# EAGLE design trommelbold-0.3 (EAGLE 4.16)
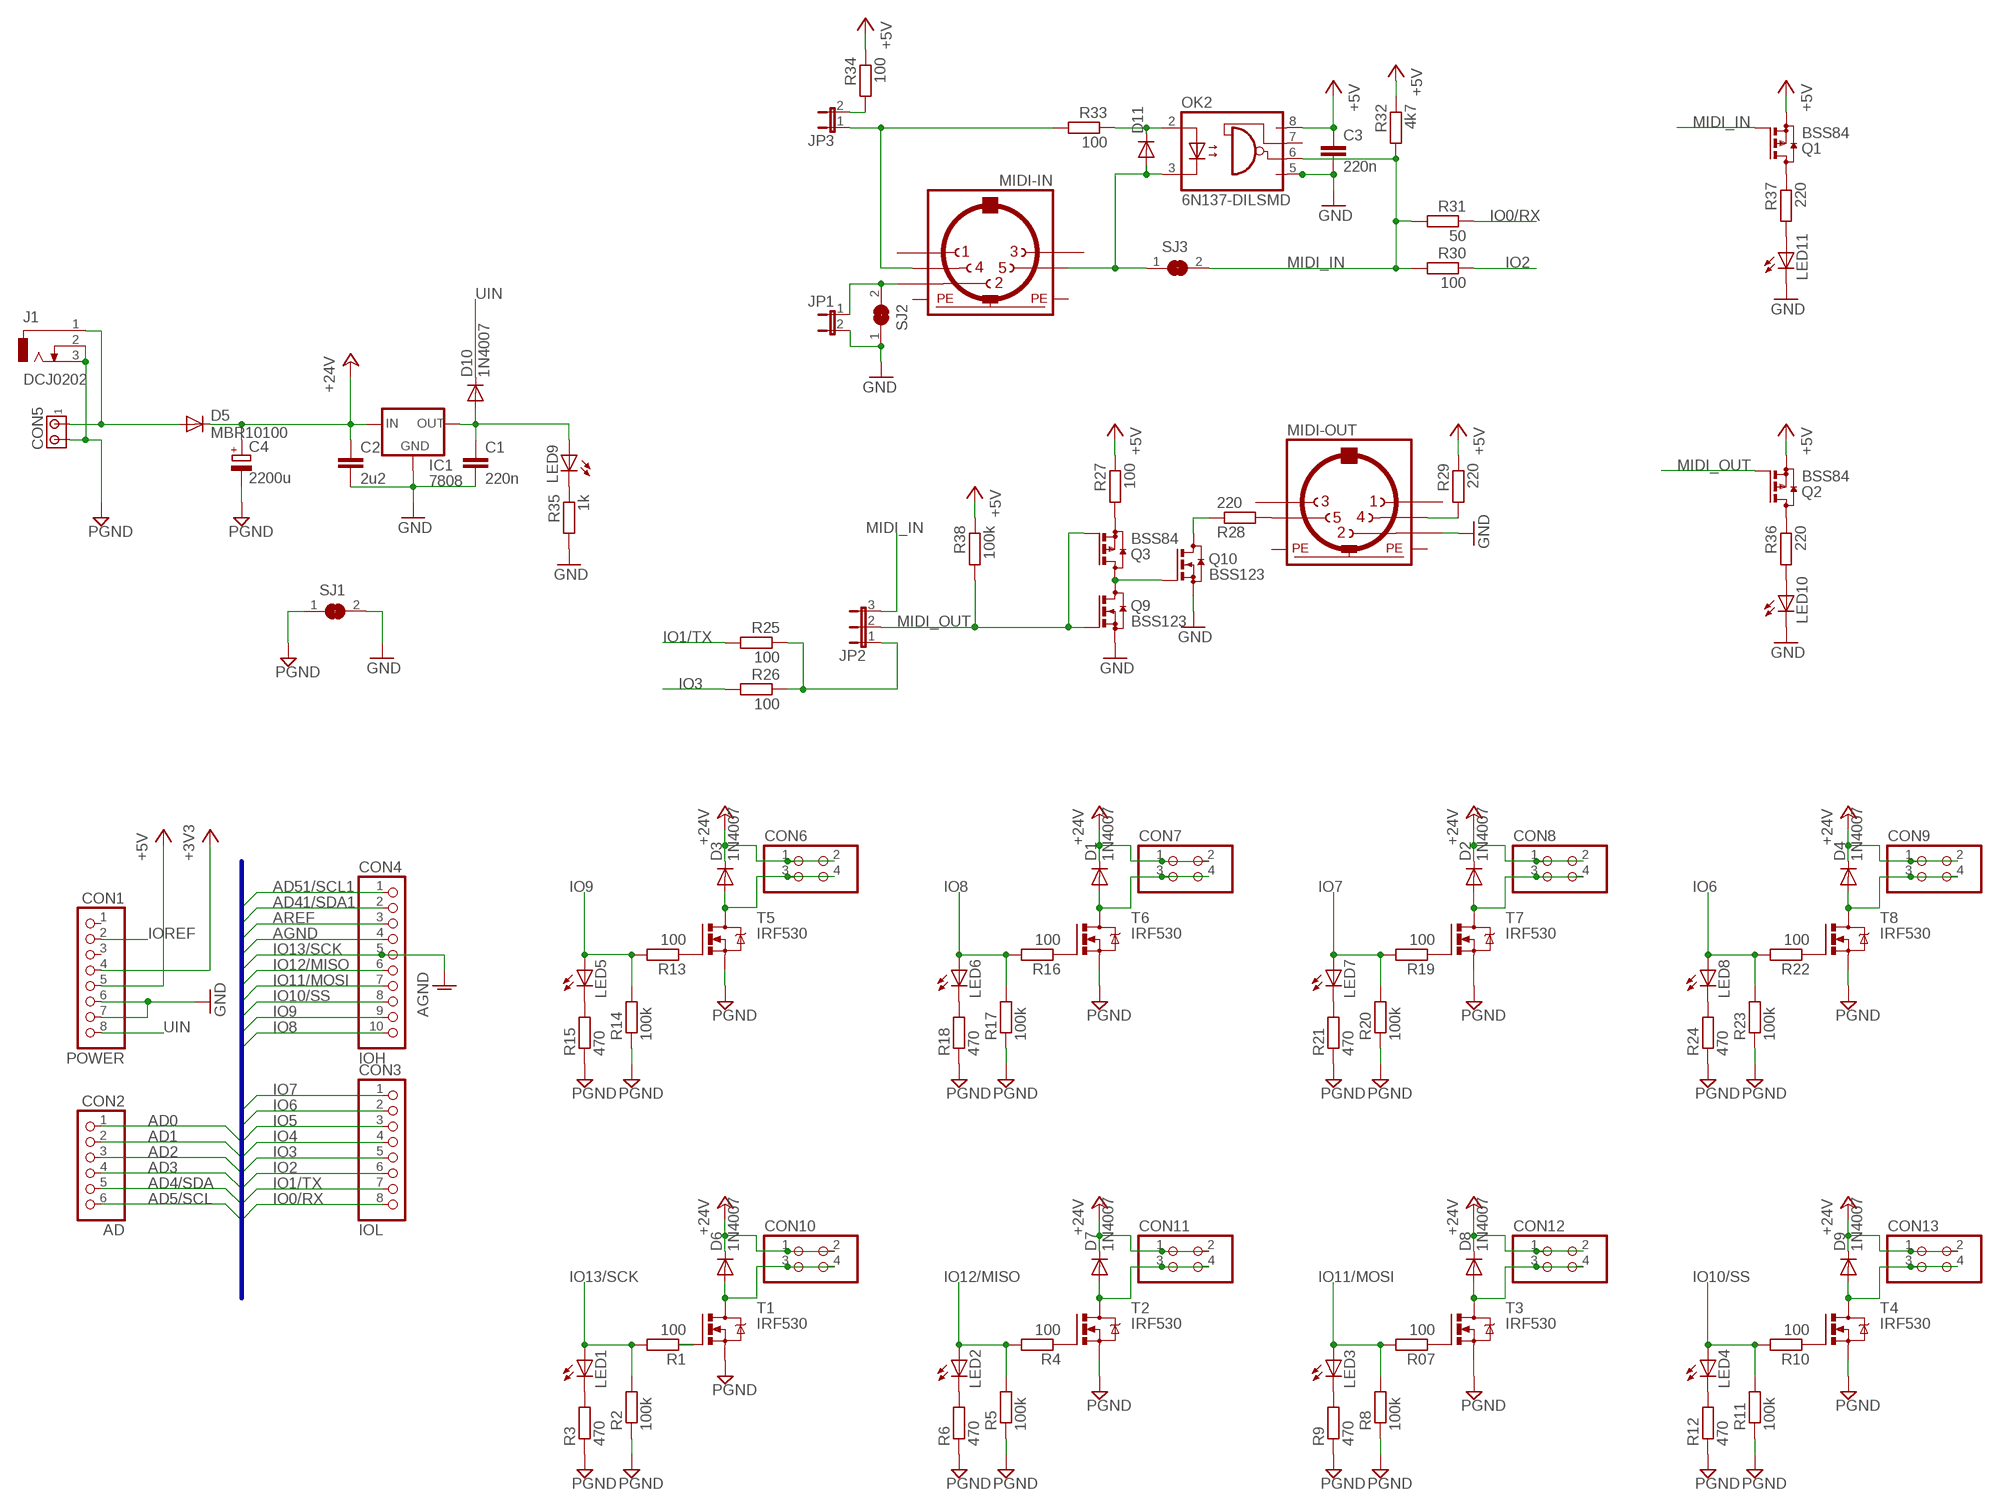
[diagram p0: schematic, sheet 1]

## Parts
C1  220n  C-EUC1206  [C1206]
C2  2u2  C-EUC1206  [C1206]
C3  220n  C-EUC1206  [C1206]
C4  2200u  CPOL-EUE7.5-18  [E7,5-18]
CON1  POWER  PINHD-1X8-L  [1X08-L]
CON2  AD  PINHD-1X6-L  [1X06-L]
CON3  IOL  PINHD-1X8-L  [1X08-L]
CON4  IOH  PINHD-1X10-L  [1X10-L]
CON5  AKL012  SCREW_TERM_X2  [SCREW_TERM_X2_381]
CON6  PINHD-2X2  [2X02]
CON7  PINHD-2X2  [2X02]
CON8  PINHD-2X2  [2X02]
CON9  PINHD-2X2  [2X02]
CON10  PINHD-2X2  [2X02]
CON11  PINHD-2X2  [2X02]
CON12  PINHD-2X2  [2X02]
CON13  PINHD-2X2  [2X02]
D1  1N4007  DIODE-D-7.5  [D-7.5]
D2  1N4007  DIODE-D-7.5  [D-7.5]
D3  1N4007  DIODE-D-7.5  [D-7.5]
D4  1N4007  DIODE-D-7.5  [D-7.5]
D5  MBR10100  DIODE-TO220V  [TO220ACS]
D6  1N4007  DIODE-D-7.5  [D-7.5]
D7  1N4007  DIODE-D-7.5  [D-7.5]
D8  1N4007  DIODE-D-7.5  [D-7.5]
D9  1N4007  DIODE-D-7.5  [D-7.5]
D10  1N4007  DIODE-DO07  [DO07]
D11  DIODE-SOD123  [SOD123]
IC1  7808  78XXS  [78XXS]
J1  DCJ0202  [DCJ0202]
JP1  JP1E  [JP1]
JP2  JP2E  [JP2]
JP3  JP1E  [JP1]
LED1  LED3MM  [LED3MM]
LED2  LED3MM  [LED3MM]
LED3  LED3MM  [LED3MM]
LED4  LED3MM  [LED3MM]
LED5  LED3MM  [LED3MM]
LED6  LED3MM  [LED3MM]
LED7  LED3MM  [LED3MM]
LED8  LED3MM  [LED3MM]
LED9  LED3MM  [LED3MM]
LED10  LED3MM  [LED3MM]
LED11  LED3MM  [LED3MM]
MIDI-IN  MAB5SH  [MAB5SH]
MIDI-OUT  MAB5SH  [MAB5SH]
OK2  6N137-DILSMD  [DIL08-SMD]
Q1  BSS84  [SOT23]
Q2  BSS84  [SOT23]
Q3  BSS84  [SOT23]
Q9  BSS123  [SOT23]
Q10  BSS123  [SOT23]
R1  100  R-EU_M1206  [M1206]
R2  100k  R-EU_M1206  [M1206]
R3  470  R-EU_M1206  [M1206]
R4  100  R-EU_M1206  [M1206]
R5  100k  R-EU_M1206  [M1206]
R6  470  R-EU_M1206  [M1206]
R07  100  R-EU_M1206  [M1206]
R8  100k  R-EU_M1206  [M1206]
R9  470  R-EU_M1206  [M1206]
R10  100  R-EU_M1206  [M1206]
R11  100k  R-EU_M1206  [M1206]
R12  470  R-EU_M1206  [M1206]
R13  100  R-EU_M1206  [M1206]
R14  100k  R-EU_M1206  [M1206]
R15  470  R-EU_M1206  [M1206]
R16  100  R-EU_M1206  [M1206]
R17  100k  R-EU_M1206  [M1206]
R18  470  R-EU_M1206  [M1206]
R19  100  R-EU_M1206  [M1206]
R20  100k  R-EU_M1206  [M1206]
R21  470  R-EU_M1206  [M1206]
R22  100  R-EU_M1206  [M1206]
R23  100k  R-EU_M1206  [M1206]
R24  470  R-EU_M1206  [M1206]
R25  100  R-EU_M1206  [M1206]
R26  100  R-EU_M1206  [M1206]
R27  100  R-EU_M1206  [M1206]
R28  220  R-EU_M1206  [M1206]
R29  220  R-EU_M1206  [M1206]
R30  100  R-EU_M1206  [M1206]
R31  50  R-EU_M1206  [M1206]
R32  4k7  R-EU_M1206  [M1206]
R33  100  R-EU_M1206  [M1206]
R34  100  R-EU_M1206  [M1206]
R35  1k  R-EU_M1206  [M1206]
R36  220  R-EU_M1206  [M1206]
R37  220  R-EU_M1206  [M1206]
R38  100k  R-EU_M1206  [M1206]
SJ1  SJ-CLOSED  [SJ]
SJ2  SJ-CLOSED  [SJ]
SJ3  SJ-CLOSED  [SJ]
T1  IRF530  [TO220BV]
T2  IRF530  [TO220BV]
T3  IRF530  [TO220BV]
T4  IRF530  [TO220BV]
T5  IRF530  [TO220BV]
T6  IRF530  [TO220BV]
T7  IRF530  [TO220BV]
T8  IRF530  [TO220BV]

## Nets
+3V3: CON1.4
+5V: C3.1 CON1.5 OK2.8(VCC) Q1.2(S) Q2.2(S) R27.1 R29.1 R32.1 R34.1 R38.1
+24V: C2.1 C4.+ CON6.1 CON6.2 CON7.1 CON7.2 CON8.1 CON8.2 CON9.1 CON9.2 CON10.1 CON10.2 CON11.1 CON11.2 CON12.1 CON12.2 CON13.1 CON13.2 D1.C D2.C D3.C D4.C D5.C D6.C D7.C D8.C D9.C IC1.IN
AD0: CON2.1
AD1: CON2.2
AD2: CON2.3
AD3: CON2.4
AD4/SDA: CON2.5
AD5/SCL: CON2.6
AD41/SDA1: CON4.2
AD51/SCL1: CON4.1
AGND: CON4.4
AREF: CON4.3
GND: C1.2 C2.2 C3.2 CON1.6 CON1.7 IC1.GND JP1.2 LED10.K(C) LED11.K(C) MIDI-OUT.2 OK2.5(GND) Q9.2(S) Q10.2(S) R35.2 SJ1.2 SJ2.1
GND1: C4.- CON5.2 J1.2 J1.3 R2.1 R3.1 R5.1 R6.1 R8.1 R9.1 R11.1 R12.1 R14.1 R15.1 R17.1 R18.1 R20.1 R21.1 R23.1 R24.1 SJ1.1 T1.S T2.S T3.S T4.S T5.S T6.S T7.S T8.S ; supply symbol labelled PGND
IO0/RX: CON3.8 R31.1
IO1/TX: CON3.7 R25.2
IO2: CON3.6 R30.1
IO3: CON3.5 R26.2
IO4: CON3.4
IO5: CON3.3
IO6: CON3.2 LED8.A R22.2 R23.2
IO7: CON3.1 LED7.A R19.2 R20.2
IO8: CON4.10 LED6.A R16.2 R17.2
IO9: CON4.9 LED5.A R13.2 R14.2
IO10/SS: CON4.8 LED4.A R10.2 R11.2
IO11/MOSI: CON4.7 LED3.A R07.2 R8.2
IO12/MISO: CON4.6 LED2.A R4.2 R5.2
IO13/SCK: CON4.5 LED1.A R1.2 R2.2 ; supply symbol labelled AGND
IOREF: CON1.2
MIDI_IN: JP2.3 OK2.6(VO) Q1.1(G) R30.2 R31.2 R32.2 SJ3.2
MIDI_OUT: JP2.2 Q2.1(G) Q3.1(G) Q9.1(G) R38.2
N$1: CON8.3 CON8.4 D2.A T7.D
N$2: CON6.3 CON6.4 D3.A T5.D
N$3: CON7.3 CON7.4 D1.A T6.D
N$4: CON9.3 CON9.4 D4.A T8.D
N$6: R19.1 T7.G
N$7: CON5.1 D5.A J1.1
N$8: R22.1 T8.G
N$9: CON10.3 CON10.4 D6.A T1.D
N$10: CON11.3 CON11.4 D7.A T2.D
N$11: CON12.3 CON12.4 D8.A T3.D
N$12: CON13.3 CON13.4 D9.A T4.D
N$13: R07.1 T3.G
N$14: R10.1 T4.G
N$15: JP3.1 MIDI-IN.4 R33.2
N$16: R1.1 T1.G
N$17: D11.C OK2.2(A) R33.1
N$18: JP3.2 R34.2
N$19: Q3.3(D) Q9.3(D) Q10.1(G)
N$20: R13.1 T5.G
N$21: R16.1 T6.G
N$22: MIDI-OUT.4 R29.2
N$23: Q10.3(D) R28.1
N$24: MIDI-OUT.5 R28.2
N$25: Q1.3(D) R37.1
N$29: LED3.K(C) R9.2
N$30: LED11.A R37.2
N$31: LED1.K(C) R3.2
N$32: JP2.1 R25.1 R26.1
N$33: LED2.K(C) R6.2
N$34: LED4.K(C) R12.2
N$35: LED8.K(C) R24.2
N$36: LED7.K(C) R21.2
N$37: LED6.K(C) R18.2
N$38: LED5.K(C) R15.2
N$40: C1.1 D10.A IC1.OUT LED9.A
N$44: R4.1 T2.G
N$45: Q2.3(D) R36.1
N$46: D11.A MIDI-IN.5 OK2.3(C) SJ3.1
N$47: LED9.K(C) R35.1
N$48: LED10.A R36.2
N$50: Q3.2(S) R27.2
N$51: JP1.1 MIDI-IN.2 SJ2.2
UIN: CON1.8 D10.C
Unconnected: CON1.1 CON1.3 MIDI-IN.1 MIDI-IN.3 MIDI-OUT.1 MIDI-OUT.3 OK2.7(VE)

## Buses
RESET,AD0,AD1,AD2,AD3,AD4/SDA,AD5/SCL,IO0/RX,IO1/TX,IO2,IO3,IO4,IO5,IO6,IO7,IO8,IO9,IO10/SS,IO11/MOSI,IO12/MISO,IO13/SCK,AREF,AGND,AD41/SDA1,AD51/SCL1

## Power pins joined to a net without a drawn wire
PE: MIDI-IN.PE MIDI-IN.PE@(PE) MIDI-OUT.PE MIDI-OUT.PE@(PE)

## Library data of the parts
C1-C3 = rcl:C-EU: CAPACITOR, European symbol
C4 = rcl:CPOL-EU: POLARIZED CAPACITOR, European symbol
CON1 CON3 = 00_pinhead_small:PINHD-1X8: PIN HEADER
CON2 = 00_pinhead_small:PINHD-1X6: PIN HEADER
CON4 = 00_pinhead_small:PINHD-1X10: PIN HEADER
CON5 = 00_sm_con:SCREW_TERM_X2
CON6-CON13 = pinhead:PINHD-2X2: PIN HEADER
D1-D11 = diode:DIODE-: DIODE
IC1 = v-reg:78XXS: VOLTAGE REGULATOR
J1 = 00_sm_con:DCJ0202: DC POWER JACK Source: DCJ0202.pdf
JP1 JP3 = jumper:JP1E: JUMPER
JP2 = jumper:JP2E: JUMPER
LED1-LED11 = led:LED: LED
MIDI-IN MIDI-OUT = con-hirschmann:MAB5SH: Female CONNECTOR 5 pins 90 deg. with shield, horizontal (DIN 41524)
OK2 = 00_sm_div:6N137: MOTOROLA OPTO COUPLER
Q1-Q3 = transistor-small-signal:BSS84: P-CHANNEL MOS FET
Q9 Q10 = transistor-small-signal:BSS123: N-CHANNEL MOS FET
R1-R6 R07 R8-R38 = rcl:R-EU_: RESISTOR, European symbol
SJ1-SJ3 = 00_sm_div:SJ-CLOSED: SMD solder JUMPER
T1-T8 = transistor-power:IRF530: HEXFET Power MOSFET

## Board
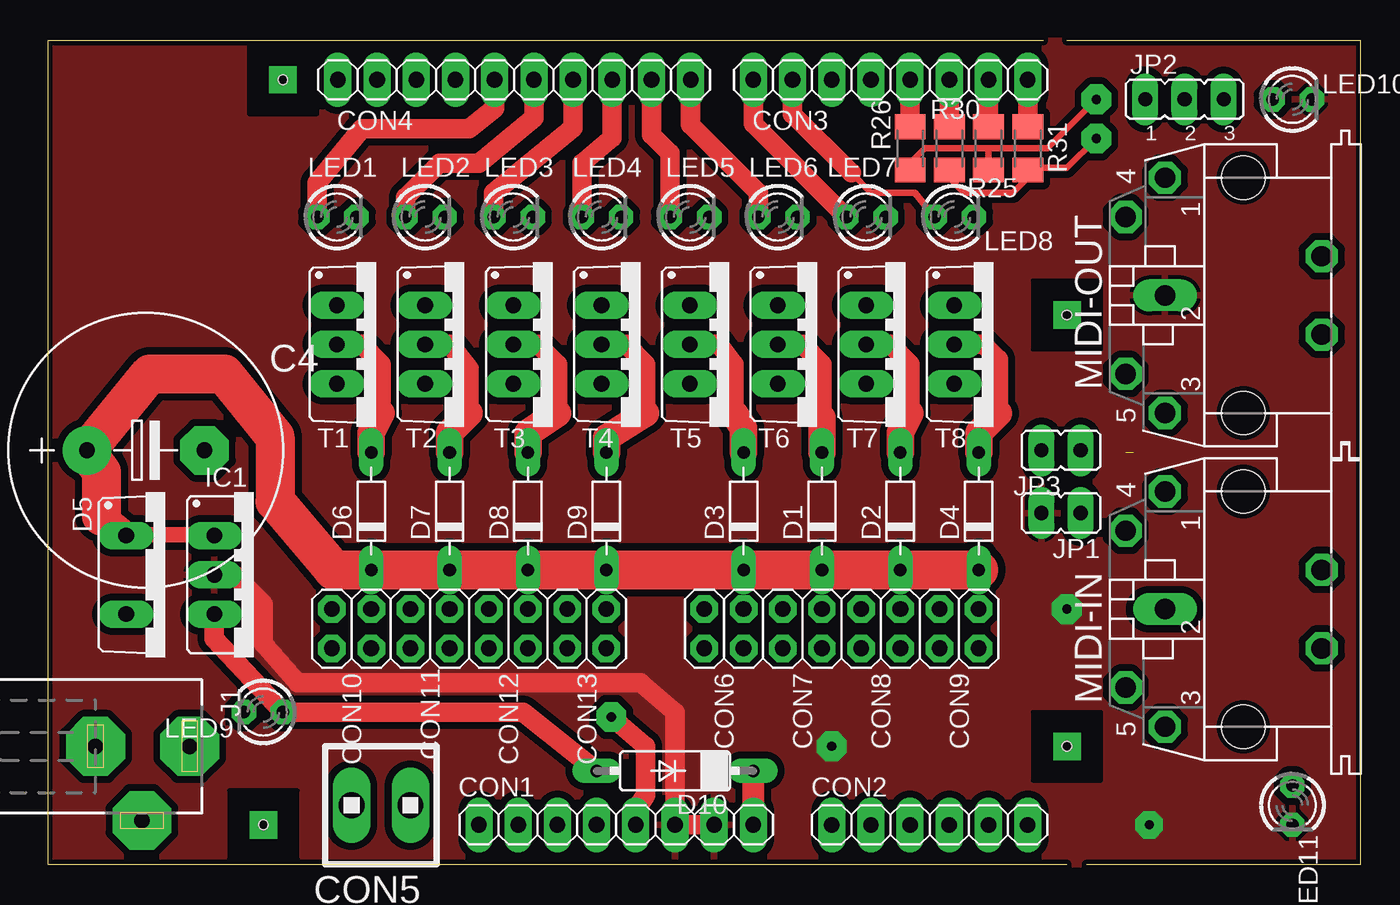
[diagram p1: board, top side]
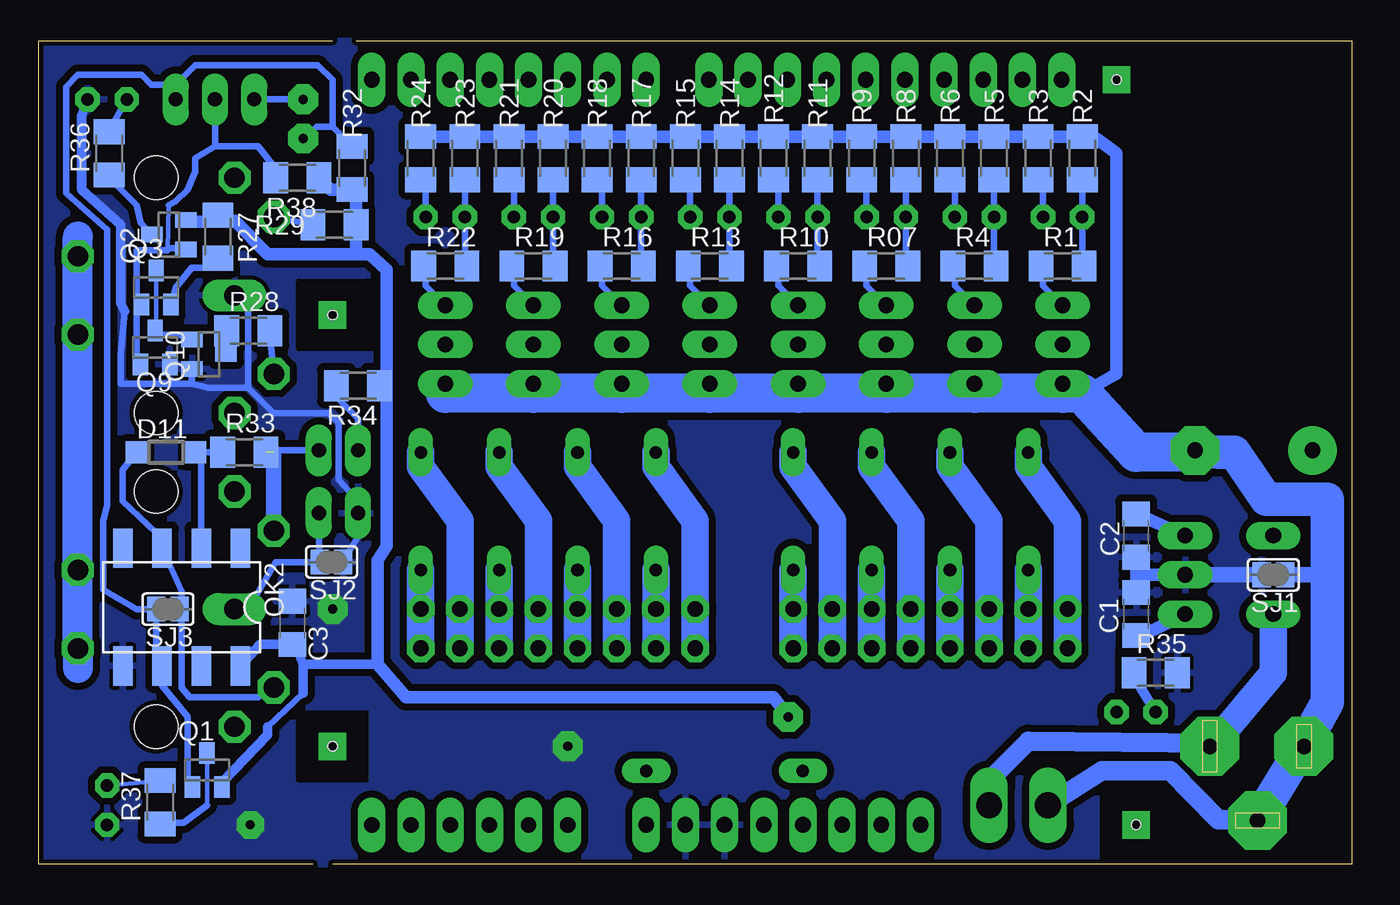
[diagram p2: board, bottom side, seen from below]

Size 85.09 x 53.34 mm. Coordinates in mm from the lower left corner, seen from the top.
Outline: 66.04,0 0,0 0,53.34 64.52,53.34
Outline: 67.31,0 85.09,0 85.09,53.34 66.04,53.34
Copper layers (1*16): Top 0.035mm / dielectric 1.5mm / Bottom 0.035mm
Design rules "default": minimum track width 10mil, minimum drill 24mil, track to track 18mil, track to pad 18mil, pad to pad 18mil, via to via 18mil, smd to smd 18mil, copper to edge 12mil, drill to drill 8mil, minimum pad ring 15mil, minimum via ring 8mil, stop-mask expansion 4mil, vias tented up to drill 0mil, thermal gap 10mil
Holes 0.6 mm at 13.97,2.54 66.04,7.62 66.04,35.56 15.24,50.8
tRestrict: area 13,48.6 to 17.5,53; area 63.8,5.4 to 68.3,9.8; area 63.8,33.3 to 68.3,37.8; area 11.7,0.3 to 16.2,4.8
bRestrict: area -1.3,28.9 to 11.4,46; area 13,48.6 to 17.5,53; area 11.7,0.3 to 16.2,4.8; area 63.8,33.3 to 68.3,37.8; area 63.8,5.4 to 68.3,9.8

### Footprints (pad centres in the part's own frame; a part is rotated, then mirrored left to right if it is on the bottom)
C1206 = smd 1.6 x 1.8: 1 -1.4,0; 2 1.4,0
E7,5-18 = drill 1.016 pad 3.15 round: + -3.81,0 | drill 1.016 pad 3.15 octagon: - 3.81,0
1X08-L = drill 1.016 pad 1.778 long: 1 -8.89,0; 2 -6.35,0; 3 -3.81,0; 4 -1.27,0; 5 1.27,0; 6 3.81,0; 7 6.35,0; 8 8.89,0
1X06-L = drill 1 pad 1.778 long: 1 -6.35,0; 2 -3.81,0; 3 -1.27,0; 4 1.27,0; 5 3.81,0; 6 6.35,0
1X10-L = drill 1.016 pad 1.778 long: 1 -11.43,0; 2 -8.89,0; 3 -6.35,0; 4 -3.81,0; 5 -1.27,0; 6 1.27,0; 7 3.81,0; 8 6.35,0; 9 8.89,0; 10 11.43,0
SCREW_TERM_X2_381 = drill 1.676 long: 1 1.905,0; 2 -1.905,0
2X02 = drill 1.016 octagon: 1 -1.27,-1.27; 2 -1.27,1.27; 3 1.27,-1.27; 4 1.27,1.27
D-7.5 = drill 0.813 long: A 3.81,0; C -3.81,0
TO220ACS = drill 1.016 long: A 2.54,-2.54; C -2.54,-2.54
DO07 = drill 0.813 long: A 5.08,0; C -5.08,0
SOD123 = smd 1.4 x 1.4: A 1.9,0; C -1.9,0
78XXS = drill 1.016 long: GND 0,-2.54; IN -2.54,-2.54; OUT 2.54,-2.54
DCJ0202 = drill 1 pad 3.81 octagon: 1 0,3.1; 2 4.8,0; 3 0,-3
JP1 = drill 0.914 long: 1 0,-1.27; 2 0,1.27
JP2 = drill 0.914 long: 1 -2.54,0; 2 0,0; 3 2.54,0
LED3MM = drill 0.813 octagon: A -1.27,0; K 1.27,0
MAB5SH = drill 1.321 octagon: 1 7.62,5.08; 3 -7.62,5.08; 4 5.08,7.62; 5 -5.08,7.62; PE -2.54,-5.08; PE@ 2.54,-5.08 | drill 1.321 long: 2 0,5.08 | hole 2.794: 7.62,0; -7.62,0
DIL08-SMD = smd 1.27 x 2.54: 1 -3.81,-3.81; 2 -1.27,-3.81; 3 1.27,-3.81; 4 3.81,-3.81; 5 3.81,3.81; 6 1.27,3.81; 7 -1.27,3.81; 8 -3.81,3.81
SOT23 = smd 1 x 1.4: 1 -0.95,-1.1; 2 0.95,-1.1; 3 0,1.1
M1206 = smd 1.6 x 2: 1 -1.4,0; 2 1.4,0
SJ = smd 1.168 x 1.6: 1 -0.762,0; 2 0.762,0
TO220BV = drill 1.016 long: D 0,-2.54; G -2.54,-2.54; S 2.54,-2.54

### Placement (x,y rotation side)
C1  13.97,16.19 90 bottom
C2  13.97,21.27 270 bottom
C3  68.64,15.62 90 bottom
C4  6.35,26.8 0 top
CON1  36.83,2.54 0 top
CON2  57.15,2.54 0 top
CON3  54.61,50.8 0 top
CON4  30.23,50.8 0 top
CON5  21.59,3.81 0 top
CON6  43.81,15.24 180 top
CON7  48.9,15.24 180 top
CON8  53.98,15.24 180 top
CON9  59.05,15.24 180 top
CON10  19.68,15.24 180 top
CON11  24.77,15.24 180 top
CON12  29.84,15.24 180 top
CON13  34.92,15.24 180 top
D1  50.16,22.86 90 top
D2  55.24,22.86 90 top
D3  45.09,22.86 90 top
D4  60.33,22.86 90 top
D5  7.62,18.73 270 top
D6  20.95,22.86 90 top
D7  26.04,22.86 90 top
D8  31.11,22.86 90 top
D9  36.2,22.86 90 top
D10  40.64,6.03 180 top
D11  76.83,26.67 180 bottom
IC1  13.34,18.73 270 top
J1  6.1,7.62 270 top
JP1  65.66,22.73 90 top
JP2  73.66,49.53 0 top
JP3  65.66,26.8 90 top
LED1  18.73,41.91 0 top
LED2  24.45,41.91 0 top
LED3  30.16,41.91 0 top
LED4  35.88,41.91 0 top
LED5  41.59,41.91 0 top
LED6  47.31,41.91 0 top
LED7  53.02,41.91 0 top
LED8  58.74,41.91 0 top
LED9  13.97,9.84 180 top
LED10  80.64,49.53 0 top
LED11  80.64,3.81 270 top
MIDI-IN  77.47,16.51 90 top
MIDI-OUT  77.47,36.83 90 top
OK2  75.82,16.64 180 bottom
Q1  74.17,6.1 0 bottom
Q2  76.64,40.77 90 bottom
Q3  77.47,37.34 0 bottom
Q9  77.53,33.46 0 bottom
Q10  74.04,33.02 270 bottom
R1  18.73,38.73 0 bottom
R2  17.46,45.72 270 bottom
R3  20.32,45.72 270 bottom
R4  24.45,38.73 0 bottom
R5  23.18,45.72 270 bottom
R6  26.04,45.72 270 bottom
R07  30.16,38.73 0 bottom
R8  28.89,45.72 270 bottom
R9  31.75,45.72 270 bottom
R10  35.88,38.73 0 bottom
R11  34.61,45.72 270 bottom
R12  37.47,45.72 270 bottom
R13  41.59,38.73 0 bottom
R14  40.32,45.72 270 bottom
R15  43.18,45.72 270 bottom
R16  47.31,38.73 0 bottom
R17  46.04,45.72 270 bottom
R18  48.9,45.72 270 bottom
R19  53.02,38.73 0 bottom
R20  51.75,45.72 270 bottom
R21  54.61,45.72 270 bottom
R22  58.74,38.73 0 bottom
R23  57.47,45.72 270 bottom
R24  60.33,45.72 270 bottom
R25  60.96,46.35 90 top
R26  55.88,46.35 90 top
R27  73.47,40.64 270 bottom
R28  71.5,34.54 0 bottom
R29  65.91,41.4 180 bottom
R30  58.42,46.35 270 top
R31  63.5,46.35 270 top
R32  64.77,45.09 90 bottom
R33  71.75,26.67 0 bottom
R34  64.39,30.99 180 bottom
R35  12.7,12.38 0 bottom
R36  80.52,46.04 90 bottom
R37  77.22,4 90 bottom
R38  68.33,44.45 180 bottom
SJ1  5.08,18.73 180 bottom
SJ2  66.1,19.56 180 bottom
SJ3  76.71,16.51 180 bottom
T1  21.27,33.66 270 top
T2  26.99,33.66 270 top
T3  32.7,33.66 270 top
T4  38.42,33.66 270 top
T5  44.13,33.66 270 top
T6  49.85,33.66 270 top
T7  55.56,33.66 270 top
T8  61.28,33.66 270 top

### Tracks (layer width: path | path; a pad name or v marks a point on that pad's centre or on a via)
+5V  (via drill 0.6 pad 1.93)
  Top 1.27: CON1.5 38.1,3.49 38.73,4.45 38.73,7.62 v36.51,9.53
  Bottom 0.406: 67.94,11.05 70.23,8.89 | 73.98,41.59 R27.1 | 68.58,14.22 C3.1 | Q1.2 73.28,4.95 73.15,5.33
  Bottom 0.61: 70.23,8.89 70.23,8.38 73.15,5.33 | 63.12,12.95 67.94,12.95 | 67.94,12.95 67.94,11.05 | OK2.8 70.74,14.22 68.58,14.22 68.45,14.22 67.94,12.95 | 62.48,30.99 62.55,30.99 R34.1
  Bottom 0.813: v36.51,9.53 37.47,10.79 61.28,10.79 63.12,12.95 63.12,19.68 62.55,20.57 62.55,30.99 62.55,38.48 63.63,39.5 64.52,39.5 | Q2.2 75.25,41.59 73.98,41.59 72.39,41.59 72.39,41.66 70.23,39.5 64.52,39.5 | 64.52,39.5 64.52,39.62 64.51,39.63 R29.1 64.51,43.69 64.52,43.69 R32.1 66.16,43.69 R38.1
+24V
  Top 1.016: D5.C 5.08,21.34 10.41,21.34 IC1.IN
  Top 1.778: 3.49,22.54 D5.C
  Top 2.54: D4.C D2.C D1.C D3.C D9.C D8.C D7.C D6.C 18.48,19.05 14.73,23.5 14.73,27.69 11.43,31.75 6.6,31.75 C4.+ 2.54,26.67 3.49,25.4 3.49,22.54
  Bottom 0.813: IC1.IN C2.1
  Bottom 1.778: D6.C CON10.1 CON10.2 | D7.C CON11.1 CON11.2 | D8.C CON12.1 CON12.2 | D9.C CON13.1 CON13.2 | D3.C CON6.1 CON6.2 | D1.C CON7.1 CON7.2 | D2.C CON8.1 CON8.2 | D4.C CON9.1 CON9.2
AD0
  Top 0.406: CON2.1 50.8,2.79
GND  (via drill 0.6 pad 1.78, 0.6 pad 1.93)
  Top 1.27: IC1.GND 12.06,18.73 13.97,16.83 13.97,14.29 16.19,11.75 38.42,11.75 40.64,9.84 CON1.6 CON1.7
  Bottom 0.406: 71.5,30.86 71.5,36.45 72.07,36.83 MIDI-OUT.2 | 71.5,30.86 74.11,30.86 75.18,31.11 | 79.5,35.81 79.76,32.96 79.76,31.11 75.18,31.11 | 75.18,31.11 Q10.2 | 71.5,30.86 69.85,29.21 66.29,29.21 65.66,28.57 65.66,24.89 64.39,23.5 JP1.2 64.39,21.21 65.41,19.56 SJ2.1 | 79.69,36.2 79.76,36.32
  Bottom 0.61: 79.5,35.81 79.69,36.2 | LED10.K 82.3,48.51 82.3,43.69 79.76,41.4 79.76,36.32
  Bottom 0.813: IC1.GND 13.97,18.73 C1.2 C2.2
  Bottom 1.016: 5.71,18.73 SJ1.2 IC1.GND
  other vias: 71.37,2.54 50.8,7.62 66.04,16.51
  pour Top: 85.09,53.34 85.09,0 0,0 0,53.34
  pour Bottom: 0,53.34 85.09,53.34 85.09,0 0,0
GND1
  Bottom 0.406: 6.22,2.86 6.22,2.92 J1.2
  Bottom 0.813: 17.46,30.48 15.24,31.75 15.24,46.04 16.51,46.99 17.46,46.99 | R24.1 57.6,47.12 57.47,46.99 R23.1 54.74,47.12 54.61,46.99 R21.1 51.88,47.12 51.75,46.99 R20.1 49.02,47.12 48.9,46.99 R18.1 46.17,47.12 46.04,46.99 R17.1 43.31,47.12 43.18,46.99 R15.1 40.45,47.12 40.32,46.99 R14.1 37.59,47.12 37.47,46.99 | 17.46,46.99 R2.1 | 17.46,46.99 17.59,47.12 R3.1 20.32,46.99 20.45,47.12 R5.1 23.18,46.99 23.31,47.12 R6.1 26.04,46.99 26.16,47.12 R8.1 28.89,46.99 29.02,47.12 R9.1 31.75,46.99 31.88,47.12 R11.1 37.34,47.12 37.47,46.99 | 37.47,46.99 R12.1
  Bottom 1.016: 1.59,18.73 SJ1.1
  Bottom 1.27: CON5.2 16.19,6.03 11.75,6.03 8.64,2.86 6.22,2.86 6.1,2.86
  Bottom 1.422: 3.17,7.62 J1.3
  Bottom 1.778: 41.59,30.48 T5.S | 47.31,30.48 T6.S | 58.74,30.48 T8.S | 53.02,30.48 T7.S | 18.73,30.48 T1.S | 24.45,30.48 T2.S | 30.16,30.48 T3.S | 35.88,30.48 T4.S
  Bottom 2.184: 6.1,2.86 3.17,7.62 1.59,10.48 1.59,18.73 1.59,23.62 5.52,23.62 7.62,26.67 8.64,26.67 C4.-
  Bottom 2.54: 58.74,30.48 53.02,30.48 47.31,30.48 41.59,30.48 35.88,30.48 30.16,30.48 24.45,30.48 18.73,30.48 17.46,30.48 13.97,26.67 10.16,26.67 arc-60 C4.-
IO0/RX
  Top 0.813: R31.1 63.5,47.62
  Top 1.27: R31.1 CON3.8
IO1/TX
  Top 0.813: R25.2 60.96,47.62
  Top 1.27: R25.2 CON3.7
IO2
  Top 0.813: R30.1 58.42,47.62
  Top 1.27: R30.1 CON3.6
IO3
  Top 0.813: R26.2 55.88,47.62
  Top 1.27: R26.2 CON3.5
IO6
  Top 0.406: LED8.A 56.2,43.5 53.34,43.5 52.07,44.77
  Top 1.27: CON3.2 48.26,48.58 52.07,44.77
  Bottom 0.406: R22.2 57.47,39.37 LED8.A R23.2
IO7
  Top 1.27: CON3.1 45.72,47.94 LED7.A
  Bottom 0.406: R19.2 51.75,39.37 51.75,41.78 | 51.75,41.78 LED7.A | 51.75,41.78 R20.2
IO8
  Top 1.27: CON4.10 41.66,47.88 46.04,43.5 LED6.A
  Bottom 0.406: R16.2 46.04,39.37 LED6.A R17.2
IO9
  Top 1.27: CON4.9 39.12,47.24 40.32,46.04 LED5.A
  Bottom 0.406: R13.2 40.32,39.37 LED5.A R14.2
IO10/SS
  Top 1.27: CON4.8 36.58,47.05 34.61,45.4 LED4.A
  Bottom 0.406: R10.2 34.61,39.37 LED4.A R11.2
IO11/MOSI
  Top 1.27: CON4.7 34.04,47.69 28.89,43.5 LED3.A
  Bottom 0.406: R07.2 28.89,39.37 LED3.A R8.2
IO12/MISO
  Top 1.27: CON4.6 31.5,48.32 27.94,45.4 25.4,45.4 23.18,43.18 LED2.A
  Bottom 0.406: R4.2 23.18,39.37 LED2.A R5.2
IO13/SCK
  Top 1.27: CON4.5 28.96,48.96 27.3,47.62 20.32,47.62 17.46,44.13 LED1.A
  Bottom 0.406: R1.2 17.46,39.37 LED1.A R2.2
MIDI_IN  (via drill 0.6 pad 1.93)
  Top 0.406: v67.94,46.99 66.04,45.09 64.14,45.09 63.5,44.45 | 63.5,44.45 R31.2 | 58.42,45.09 R30.2 58.42,44.45 59.37,43.5 62.55,43.5 63.5,44.45
  Bottom 0.406: 76.2,50.48 JP2.3 | 76.2,50.48 74.93,51.75 66.99,51.75 66.04,50.8 66.04,47.75 | 76.2,50.48 77.79,50.48 78.42,51.12 82.55,51.12 83.31,50.35 83.31,43.43 80.64,41.08 80.64,23.24 80.9,22.23 80.9,17.78 78.74,16.51 SJ3.2 77.47,13.97 OK2.6 77.09,11.56 75.44,9.53 75.44,5.46 Q1.1 | 66.04,47.75 R32.2 | v67.94,46.99 67.06,47.75 66.04,47.75
MIDI_OUT
  Bottom 0.305: 76.71,39.75 76.64,42.67
  Bottom 0.406: 76.64,42.67 76.2,42.93 75.44,43.69 74.93,44.83 74.93,45.72 73.66,46.48 | Q2.1 75.82,39.88 76.71,39.88 76.71,39.75 78.74,39.75 78.74,36.32 Q3.1 78.74,36.07 78.74,32.77 Q9.1 | R38.2 69.85,45.21 70.87,46.48 73.66,46.48 | 73.66,46.48 JP2.2
N$1
  Top 1.27: T7.D 54.61,33.66 55.88,32.38 55.88,29.21
  Top 1.778: 55.88,29.21 55.24,27.94 D2.A
  Bottom 1.778: D2.A 55.24,25.72 52.7,22.23 CON8.3 CON8.4
N$2
  Top 1.27: T5.D 43.5,33.66 44.45,32.38 44.45,29.21
  Top 1.778: 44.45,29.21 45.09,28.26 D3.A
  Bottom 1.778: D3.A 45.09,25.72 42.55,22.23 CON6.3 CON6.4
N$3
  Top 1.27: T6.D 48.9,33.66 50.16,32.38 50.16,28.89
  Top 1.778: D1.A 50.16,28.89
  Bottom 1.778: D1.A 50.16,25.72 47.62,22.23 CON7.3 CON7.4
N$4
  Top 1.27: T8.D 60.64,33.66 61.59,32.7 61.59,29.21
  Top 1.778: D4.A 60.33,27.94 61.59,29.21
  Bottom 1.778: D4.A 60.33,25.72 57.78,22.23 CON9.3 CON9.4
N$5  (via drill 0.6 pad 1.78)
  other vias: 13.97,2.54
N$6
  Bottom 0.406: R19.1 54.29,38.6 54.29,37.47 T7.G
N$7
  Bottom 1.27: CON5.1 23.5,5.4 20.95,7.94 8.89,7.81
  Bottom 1.422: J1.1 8.89,7.81
  Bottom 1.778: 8.89,7.81 5.08,12.38 D5.A
N$8
  Bottom 0.406: R22.1 60.01,38.73 60.01,37.47 T8.G
N$9
  Top 1.27: T1.D 20.32,33.66 21.59,32.38 21.59,29.21
  Top 1.778: 21.59,29.21 20.95,27.94 D6.A
  Bottom 1.778: D6.A 20.95,25.72 18.41,22.23 CON10.3 CON10.4
N$10
  Top 1.27: T2.D 26.04,33.66 27.3,32.07 27.3,29.21
  Top 1.778: D7.A 26.04,27.94 27.3,29.21
  Bottom 1.778: D7.A 26.04,25.72 23.5,22.23 CON11.3 CON11.4
N$11
  Top 1.27: T3.D 31.75,33.66 33.02,32.38 33.02,29.21
  Top 1.778: 33.02,29.21 31.11,27.94 D8.A
  Bottom 1.778: D8.A 31.11,25.72 28.57,22.23 CON12.3 CON12.4
N$12
  Top 1.27: T4.D 37.47,33.66 38.73,32.38 38.73,29.21
  Top 1.778: 38.73,29.21 36.2,27.62 D9.A
  Bottom 1.778: D9.A 36.2,25.72 33.66,22.23 CON13.3 CON13.4
N$13
  Bottom 0.406: R07.1 31.43,38.73 31.43,37.47 T3.G
N$14
  Bottom 0.406: R10.1 37.15,38.73 37.15,37.47 T4.G
N$15  (1 unrouted)
  Bottom 0.406: JP3.1 69.6,26.8 69.85,26.67
  Bottom 1.016: MIDI-IN.4 69.85,26.67
N$16
  Bottom 0.406: R1.1 20,38.73 20,37.47 T1.G
N$17
  Bottom 0.406: 73.16,26.8 R33.1 74.55,26.67 | 74.55,26.67 D11.C | OK2.2 74.55,26.67
N$18
  Bottom 0.406: R34.2 65.79,30.23 64.39,28.83 JP3.2
N$19
  Bottom 0.305: 77.47,34.54 Q3.3
  Bottom 0.406: 77.47,34.54 Q9.3 77.47,34.29 75.95,34.29 Q10.1
N$20
  Bottom 0.406: R13.1 42.86,38.6 42.86,37.47 T5.G
N$21
  Bottom 0.406: R16.1 48.58,38.73 48.58,37.47 T6.G
N$22
  Bottom 0.406: R29.2 MIDI-OUT.4
N$23
  Bottom 0.406: R28.1 Q10.3
N$24
  Bottom 0.406: MIDI-OUT.5 R28.2
N$25
  Bottom 0.305: 74.17,3.81 Q1.3
  Bottom 0.406: 74.17,3.81 75.69,2.67 76.83,2.67 R37.1
N$26  (via drill 0.6 pad 1.78)
  other vias: 15.24,50.8
N$27  (via drill 0.6 pad 1.78)
  other vias: 66.04,35.56
N$28  (via drill 0.6 pad 1.78)
  other vias: 66.04,7.62
N$29
  Bottom 0.406: LED3.K 31.43,44.13 R9.2
N$30
  Bottom 0.305: R37.2 LED11.A
N$31
  Bottom 0.406: LED1.K 20,44.32 R3.2
N$32  (via drill 0.6 pad 1.93)
  Top 0.406: R26.1 55.88,45.4 56.83,46.35 60.96,46.35 | 60.96,46.35 R25.1 | 60.96,46.35 64.77,46.35 v67.94,49.53
  Bottom 0.406: v67.94,49.53 JP2.1
N$33
  Bottom 0.406: LED2.K 25.72,44.32 R6.2
N$34
  Bottom 0.406: LED4.K 37.15,44.13 R12.2
N$35
  Bottom 0.406: LED8.K 60.01,43.81 R24.2
N$36
  Bottom 0.406: LED7.K 54.29,43.81 R21.2
N$37
  Bottom 0.406: LED6.K 48.58,44.45 R18.2
N$38
  Bottom 0.406: LED5.K 42.86,44.32 R15.2
N$39  (via drill 0.6 pad 2.54)
  other vias: 77.47,44.45
N$40
  Top 1.27: D10.A 30.8,9.84 LED9.A 10.79,14.61 IC1.OUT
  Bottom 0.813: C1.1 13.34,14.92 IC1.OUT
N$41  (via drill 0.6 pad 2.54)
  other vias: 77.47,29.21
N$42  (via drill 0.6 pad 2.54)
  other vias: 77.47,24.13
N$43  (via drill 0.6 pad 2.54)
  other vias: 77.47,8.89
N$44
  Bottom 0.406: R4.1 25.72,38.6 25.72,37.47 T2.G
N$45
  Bottom 0.406: Q2.3 78.49,41.53 78.74,42.67 80.52,44.45 R36.1 80.52,44.7
N$46
  Bottom 0.406: MIDI-IN.5 70.87,10.79 75.31,10.79 75.82,11.43 75.82,16.51 | D11.A 79.63,25.53 79.63,23.5 77.47,21.46 77.09,20.32 OK2.3 75.82,17.65 75.82,16.51 | 75.82,16.51 SJ3.1
N$47
  Bottom 0.61: R35.1 14.29,12.38 LED9.K
N$48
  Bottom 0.406: R36.2 80.52,47.5 LED10.A
N$50
  Bottom 0.406: R27.2 74.17,38.86 74.17,38.61 75.18,38.61 76.2,37.34 76.45,36.32 Q3.2
N$51
  Bottom 0.406: MIDI-IN.2 71.5,16.51 69.72,19.56 SJ2.2 JP1.1
PE
  Bottom 1.93: 82.55,12.7 MIDI-IN.PE MIDI-IN.PE@ MIDI-OUT.PE MIDI-OUT.PE@ 82.55,40.64
UIN
  Top 1.422: CON1.8 D10.C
